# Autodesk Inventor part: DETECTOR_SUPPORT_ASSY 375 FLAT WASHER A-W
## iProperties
Shininess: 64.0
Length Units: 11272
Angle Units: 11279
Time Units: 11290
Mass Units: 11286
Length Display Precision: 3
Angle Display Precision: 2
Compacted: True
Part Number: DETECTOR_SUPPORT_ASSY 375 FLAT WASHER A-W
Document SubType Name: Modeling
Created: 2004-08
Designer: John Blackburn
Material: STAINLESS_STEEL, AUSTENITIC
Manufacturer: Standard
Standards Organization: Custom
Density: 0.0
Volumn: 0.0
Area: 0.0
PropertySet Name: Model Information
Control State: 0
Master: False
Checked Out: False
Author: John Blackburn
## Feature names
1. Base1
